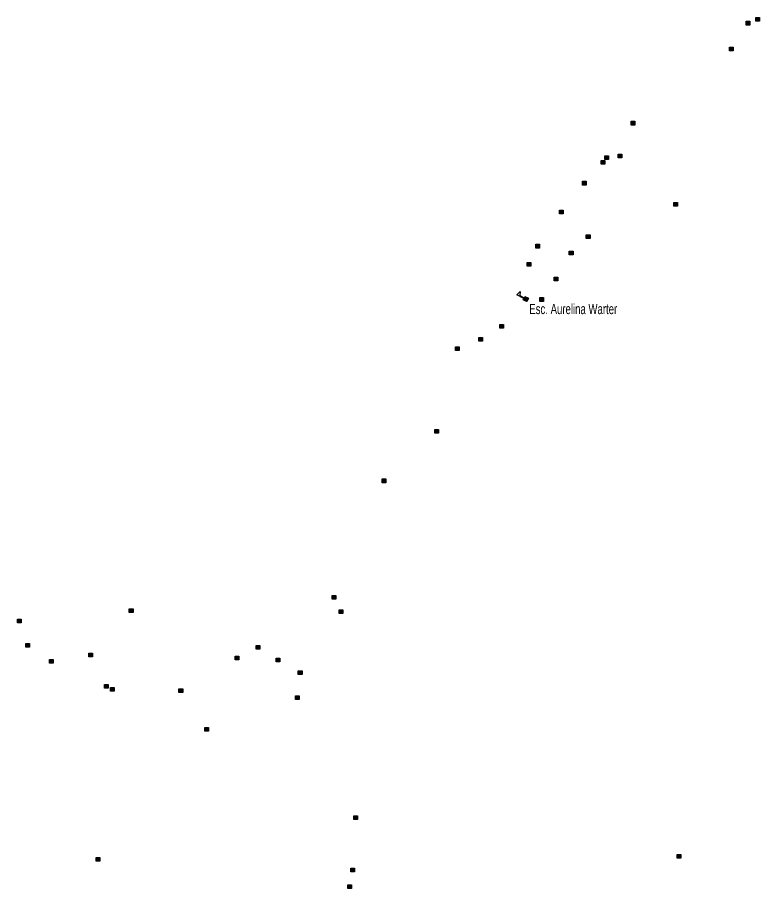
# Model space of a CAD drawing. Extents: x 649.2 to 674.4, y 7040 to 7068.1.
# Drawn here: x 668.34 to 674.14, y 7054.07 to 7060.87 of the extents above; entities that cross this region are included whole.
import ezdxf

# ---------------------------------------------------------------- set-up
doc = ezdxf.new("R2010")
doc.units = 0
doc.header["$LTSCALE"] = 0.032
doc.layers.add('2', color=7, linetype='Continuous', lineweight=25)
doc.layers.add('4', color=7, linetype='Continuous', lineweight=25)
doc.layers.add('61', color=7, linetype='Continuous')

msp = doc.modelspace()

# ---------------------------------------------------------------- hatches: boundary and pattern name
at = {"layer": '2'}
for points in [[(674.0314, 7060.8432), (674.0604, 7060.8432), (674.0604, 7060.8142), (674.0314, 7060.8142)], [(674.1065, 7060.8736), (674.1355, 7060.8736), (674.1355, 7060.8446), (674.1065, 7060.8446)], [(673.9007, 7060.641), (673.9297, 7060.641), (673.9297, 7060.612), (673.9007, 7060.612)], [(673.132, 7060.0621), (673.161, 7060.0621), (673.161, 7060.0331), (673.132, 7060.0331)], [(673.0318, 7059.8053), (673.0608, 7059.8053), (673.0608, 7059.7763), (673.0318, 7059.7763)], [(672.8977, 7059.7559), (672.9267, 7059.7559), (672.9267, 7059.7269), (672.8977, 7059.7269)], [(672.9259, 7059.7926), (672.9549, 7059.7926), (672.9549, 7059.7636), (672.9259, 7059.7636)], [(672.7523, 7059.5936), (672.7813, 7059.5936), (672.7813, 7059.5646), (672.7523, 7059.5646)], [(673.4666, 7059.429), (673.4956, 7059.429), (673.4956, 7059.4), (673.4666, 7059.4)], [(672.5716, 7059.3683), (672.6006, 7059.3683), (672.6006, 7059.3393), (672.5716, 7059.3393)], [(672.782, 7059.1752), (672.811, 7059.1752), (672.811, 7059.1462), (672.782, 7059.1462)], [(672.3871, 7059.1017), (672.4161, 7059.1017), (672.4161, 7059.0727), (672.3871, 7059.0727)], [(672.6495, 7059.0483), (672.6785, 7059.0483), (672.6785, 7059.0193), (672.6495, 7059.0193)], [(672.3194, 7058.959), (672.3484, 7058.959), (672.3484, 7058.93), (672.3194, 7058.93)], [(672.5298, 7058.8451), (672.5588, 7058.8451), (672.5588, 7058.8161), (672.5298, 7058.8161)], [(672.4189, 7058.6851), (672.4479, 7058.6851), (672.4479, 7058.6561), (672.4189, 7058.6561)], [(672.1066, 7058.4745), (672.1356, 7058.4745), (672.1356, 7058.4455), (672.1066, 7058.4455)], [(671.9414, 7058.3731), (671.9704, 7058.3731), (671.9704, 7058.3441), (671.9414, 7058.3441)], [(671.76, 7058.3018), (671.789, 7058.3018), (671.789, 7058.2728), (671.76, 7058.2728)], [(671.5997, 7057.656), (671.6287, 7057.656), (671.6287, 7057.627), (671.5997, 7057.627)], [(671.1864, 7057.2689), (671.2154, 7057.2689), (671.2154, 7057.2399), (671.1864, 7057.2399)], [(670.7977, 7056.3587), (670.8267, 7056.3587), (670.8267, 7056.3297), (670.7977, 7056.3297)], [(669.2124, 7056.2548), (669.2414, 7056.2548), (669.2414, 7056.2258), (669.2124, 7056.2258)], [(670.8507, 7056.2463), (670.8797, 7056.2463), (670.8797, 7056.2173), (670.8507, 7056.2173)], [(668.3386, 7056.1738), (668.3676, 7056.1738), (668.3676, 7056.1448), (668.3386, 7056.1448)], [(668.4038, 7055.9835), (668.4328, 7055.9835), (668.4328, 7055.9545), (668.4038, 7055.9545)], [(670.2035, 7055.9674), (670.2325, 7055.9674), (670.2325, 7055.9384), (670.2035, 7055.9384)], [(668.5888, 7055.8584), (668.6178, 7055.8584), (668.6178, 7055.8294), (668.5888, 7055.8294)], [(668.8971, 7055.9095), (668.9261, 7055.9095), (668.9261, 7055.8805), (668.8971, 7055.8805)], [(670.039, 7055.8856), (670.068, 7055.8856), (670.068, 7055.8566), (670.039, 7055.8566)], [(670.3593, 7055.8691), (670.3883, 7055.8691), (670.3883, 7055.8401), (670.3593, 7055.8401)], [(670.5326, 7055.7697), (670.5616, 7055.7697), (670.5616, 7055.7407), (670.5326, 7055.7407)], [(669.0186, 7055.6628), (669.0476, 7055.6628), (669.0476, 7055.6338), (669.0186, 7055.6338)], [(669.0662, 7055.6399), (669.0952, 7055.6399), (669.0952, 7055.6109), (669.0662, 7055.6109)], [(669.6004, 7055.6293), (669.6294, 7055.6293), (669.6294, 7055.6003), (669.6004, 7055.6003)], [(670.5106, 7055.5742), (670.5396, 7055.5742), (670.5396, 7055.5452), (670.5106, 7055.5452)], [(669.8013, 7055.329), (669.8303, 7055.329), (669.8303, 7055.3), (669.8013, 7055.3)], [(670.9666, 7054.6382), (670.9956, 7054.6382), (670.9956, 7054.6092), (670.9666, 7054.6092)], [(668.9534, 7054.3132), (668.9824, 7054.3132), (668.9824, 7054.2842), (668.9534, 7054.2842)], [(673.4916, 7054.3352), (673.5206, 7054.3352), (673.5206, 7054.3062), (673.4916, 7054.3062)], [(670.9437, 7054.2298), (670.9727, 7054.2298), (670.9727, 7054.2008), (670.9437, 7054.2008)], [(670.9195, 7054.0987), (670.9485, 7054.0987), (670.9485, 7054.0697), (670.9195, 7054.0697)]]:
    msp.add_hatch(color=256, dxfattribs=at).paths.add_polyline_path(points)
at = {"layer": '4'}
msp.add_hatch(color=256, dxfattribs=at).paths.add_polyline_path([(672.3155, 7058.6541), (672.2889, 7058.6679), (672.3026, 7058.6946), (672.3293, 7058.6808)])

# ---------------------------------------------------------------- linework, layer by layer
at = {"layer": '2'}
for points in [[(674.0314, 7060.8432), (674.0604, 7060.8432), (674.0604, 7060.8142), (674.0314, 7060.8142)], [(674.1065, 7060.8736), (674.1355, 7060.8736), (674.1355, 7060.8446), (674.1065, 7060.8446)], [(673.9007, 7060.641), (673.9297, 7060.641), (673.9297, 7060.612), (673.9007, 7060.612)], [(673.132, 7060.0621), (673.161, 7060.0621), (673.161, 7060.0331), (673.132, 7060.0331)], [(673.0318, 7059.8053), (673.0608, 7059.8053), (673.0608, 7059.7763), (673.0318, 7059.7763)], [(672.8977, 7059.7559), (672.9267, 7059.7559), (672.9267, 7059.7269), (672.8977, 7059.7269)], [(672.9259, 7059.7926), (672.9549, 7059.7926), (672.9549, 7059.7636), (672.9259, 7059.7636)], [(672.7523, 7059.5936), (672.7813, 7059.5936), (672.7813, 7059.5646), (672.7523, 7059.5646)], [(673.4666, 7059.429), (673.4956, 7059.429), (673.4956, 7059.4), (673.4666, 7059.4)], [(672.5716, 7059.3683), (672.6006, 7059.3683), (672.6006, 7059.3393), (672.5716, 7059.3393)], [(672.782, 7059.1752), (672.811, 7059.1752), (672.811, 7059.1462), (672.782, 7059.1462)], [(672.3871, 7059.1017), (672.4161, 7059.1017), (672.4161, 7059.0727), (672.3871, 7059.0727)], [(672.6495, 7059.0483), (672.6785, 7059.0483), (672.6785, 7059.0193), (672.6495, 7059.0193)], [(672.3194, 7058.959), (672.3484, 7058.959), (672.3484, 7058.93), (672.3194, 7058.93)], [(672.5298, 7058.8451), (672.5588, 7058.8451), (672.5588, 7058.8161), (672.5298, 7058.8161)], [(672.4189, 7058.6851), (672.4479, 7058.6851), (672.4479, 7058.6561), (672.4189, 7058.6561)], [(672.1066, 7058.4745), (672.1356, 7058.4745), (672.1356, 7058.4455), (672.1066, 7058.4455)], [(671.9414, 7058.3731), (671.9704, 7058.3731), (671.9704, 7058.3441), (671.9414, 7058.3441)], [(671.76, 7058.3018), (671.789, 7058.3018), (671.789, 7058.2728), (671.76, 7058.2728)], [(671.5997, 7057.656), (671.6287, 7057.656), (671.6287, 7057.627), (671.5997, 7057.627)], [(671.1864, 7057.2689), (671.2154, 7057.2689), (671.2154, 7057.2399), (671.1864, 7057.2399)], [(670.7977, 7056.3587), (670.8267, 7056.3587), (670.8267, 7056.3297), (670.7977, 7056.3297)], [(669.2124, 7056.2548), (669.2414, 7056.2548), (669.2414, 7056.2258), (669.2124, 7056.2258)], [(670.8507, 7056.2463), (670.8797, 7056.2463), (670.8797, 7056.2173), (670.8507, 7056.2173)], [(668.3386, 7056.1738), (668.3676, 7056.1738), (668.3676, 7056.1448), (668.3386, 7056.1448)], [(668.4038, 7055.9835), (668.4328, 7055.9835), (668.4328, 7055.9545), (668.4038, 7055.9545)], [(670.2035, 7055.9674), (670.2325, 7055.9674), (670.2325, 7055.9384), (670.2035, 7055.9384)], [(668.5888, 7055.8584), (668.6178, 7055.8584), (668.6178, 7055.8294), (668.5888, 7055.8294)], [(668.8971, 7055.9095), (668.9261, 7055.9095), (668.9261, 7055.8805), (668.8971, 7055.8805)], [(670.039, 7055.8856), (670.068, 7055.8856), (670.068, 7055.8566), (670.039, 7055.8566)], [(670.3593, 7055.8691), (670.3883, 7055.8691), (670.3883, 7055.8401), (670.3593, 7055.8401)], [(670.5326, 7055.7697), (670.5616, 7055.7697), (670.5616, 7055.7407), (670.5326, 7055.7407)], [(669.0186, 7055.6628), (669.0476, 7055.6628), (669.0476, 7055.6338), (669.0186, 7055.6338)], [(669.0662, 7055.6399), (669.0952, 7055.6399), (669.0952, 7055.6109), (669.0662, 7055.6109)], [(669.6004, 7055.6293), (669.6294, 7055.6293), (669.6294, 7055.6003), (669.6004, 7055.6003)], [(670.5106, 7055.5742), (670.5396, 7055.5742), (670.5396, 7055.5452), (670.5106, 7055.5452)], [(669.8013, 7055.329), (669.8303, 7055.329), (669.8303, 7055.3), (669.8013, 7055.3)], [(670.9666, 7054.6382), (670.9956, 7054.6382), (670.9956, 7054.6092), (670.9666, 7054.6092)], [(668.9534, 7054.3132), (668.9824, 7054.3132), (668.9824, 7054.2842), (668.9534, 7054.2842)], [(673.4916, 7054.3352), (673.5206, 7054.3352), (673.5206, 7054.3062), (673.4916, 7054.3062)], [(670.9437, 7054.2298), (670.9727, 7054.2298), (670.9727, 7054.2008), (670.9437, 7054.2008)], [(670.9195, 7054.0987), (670.9485, 7054.0987), (670.9485, 7054.0697), (670.9195, 7054.0697)]]:
    msp.add_lwpolyline(points, close=True, dxfattribs=at)
at = {"layer": '4'}
msp.add_line((672.2946, 7058.679), (672.2969, 7058.6834), dxfattribs=at)
for points in [[(672.2946, 7058.679), (672.2391, 7058.7077), (672.2662, 7058.733), (672.2618, 7058.7016), (672.2969, 7058.6834)], [(672.3155, 7058.6541), (672.2889, 7058.6679), (672.3026, 7058.6946), (672.3293, 7058.6808)]]:
    msp.add_lwpolyline(points, close=True, dxfattribs=at)

# ---------------------------------------------------------------- texts
at = {"layer": '61', "width": 0.7}
msp.add_text('Esc. Aurelina Warter', height=0.08, dxfattribs=at).set_placement((672.3369, 7058.5565))

doc.saveas('drawing.dxf')
